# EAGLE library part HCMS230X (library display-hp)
LED DISPLAY 4-character dot matrix
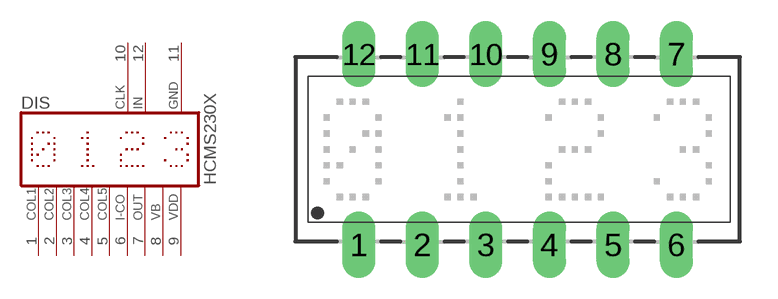
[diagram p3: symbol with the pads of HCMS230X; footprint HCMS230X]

Designator prefix DIS

## HCMS230X (OC_FARNELL: unknown; OC_NEWARK: unknown)  [HCMS230X]
1  COL1  in
2  COL2  in
3  COL3  in
4  COL4  in
5  COL5  in
6  I-CO  in
7  OUT  in
8  VB  in
9  VDD  pwr
10  CLK  in
11  GND  pwr
12  IN  in

## Footprint HCMS230X (pad centres in mm)
LED DISPLAY 4-mm 4 character dot matrix
drill 0.813 long: 1 -6.35,-3.81; 2 -3.81,-3.81; 3 -1.27,-3.81; 4 1.27,-3.81; 5 3.81,-3.81; 6 6.35,-3.81; 7 6.35,3.81; 8 3.81,3.81; 9 1.27,3.81; 10 -1.27,3.81; 11 -3.81,3.81; 12 -6.35,3.81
